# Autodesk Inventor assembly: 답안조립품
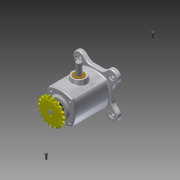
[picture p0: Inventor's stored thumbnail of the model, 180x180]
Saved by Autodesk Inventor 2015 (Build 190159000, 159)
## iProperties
Created: 2016-05
Part Number: 답안조립품
Document SubType Name: Assembly
Designer: Administrator
Author: Administrator
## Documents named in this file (11)
- C:\Users\Administrator\Desktop\460507V1003\답안조립품.iam
- C:\Users\Administrator\Desktop\460507V1003\본체.ipt
- C:\Users\Administrator\Desktop\460507V1003\편심축.ipt
- C:\Users\Administrator\Desktop\460507V1003\커버.ipt
- C:\Users\Administrator\Desktop\460507V1003\M4x0.7x12.ipt
- C:\Users\Administrator\Desktop\460507V1003\베어링-6203.ipt
- C:\Users\Administrator\Desktop\460507V1003\오일실.ipt
- C:\Users\Administrator\Desktop\460507V1003\스프로킷.ipt
- C:\Users\Administrator\Desktop\460507V1003\키5x5.ipt
- C:\Users\Administrator\Desktop\460507V1003\부시.ipt
- C:\Users\Administrator\Desktop\460507V1003\슬라이더.ipt
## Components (2 placed, 1 different names)
1. M4x0.7x12:1
2. M4x0.7x12:2
